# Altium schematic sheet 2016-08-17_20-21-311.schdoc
size 387 x 177 mm; SheetNumber: 1; SheetTotal: 1
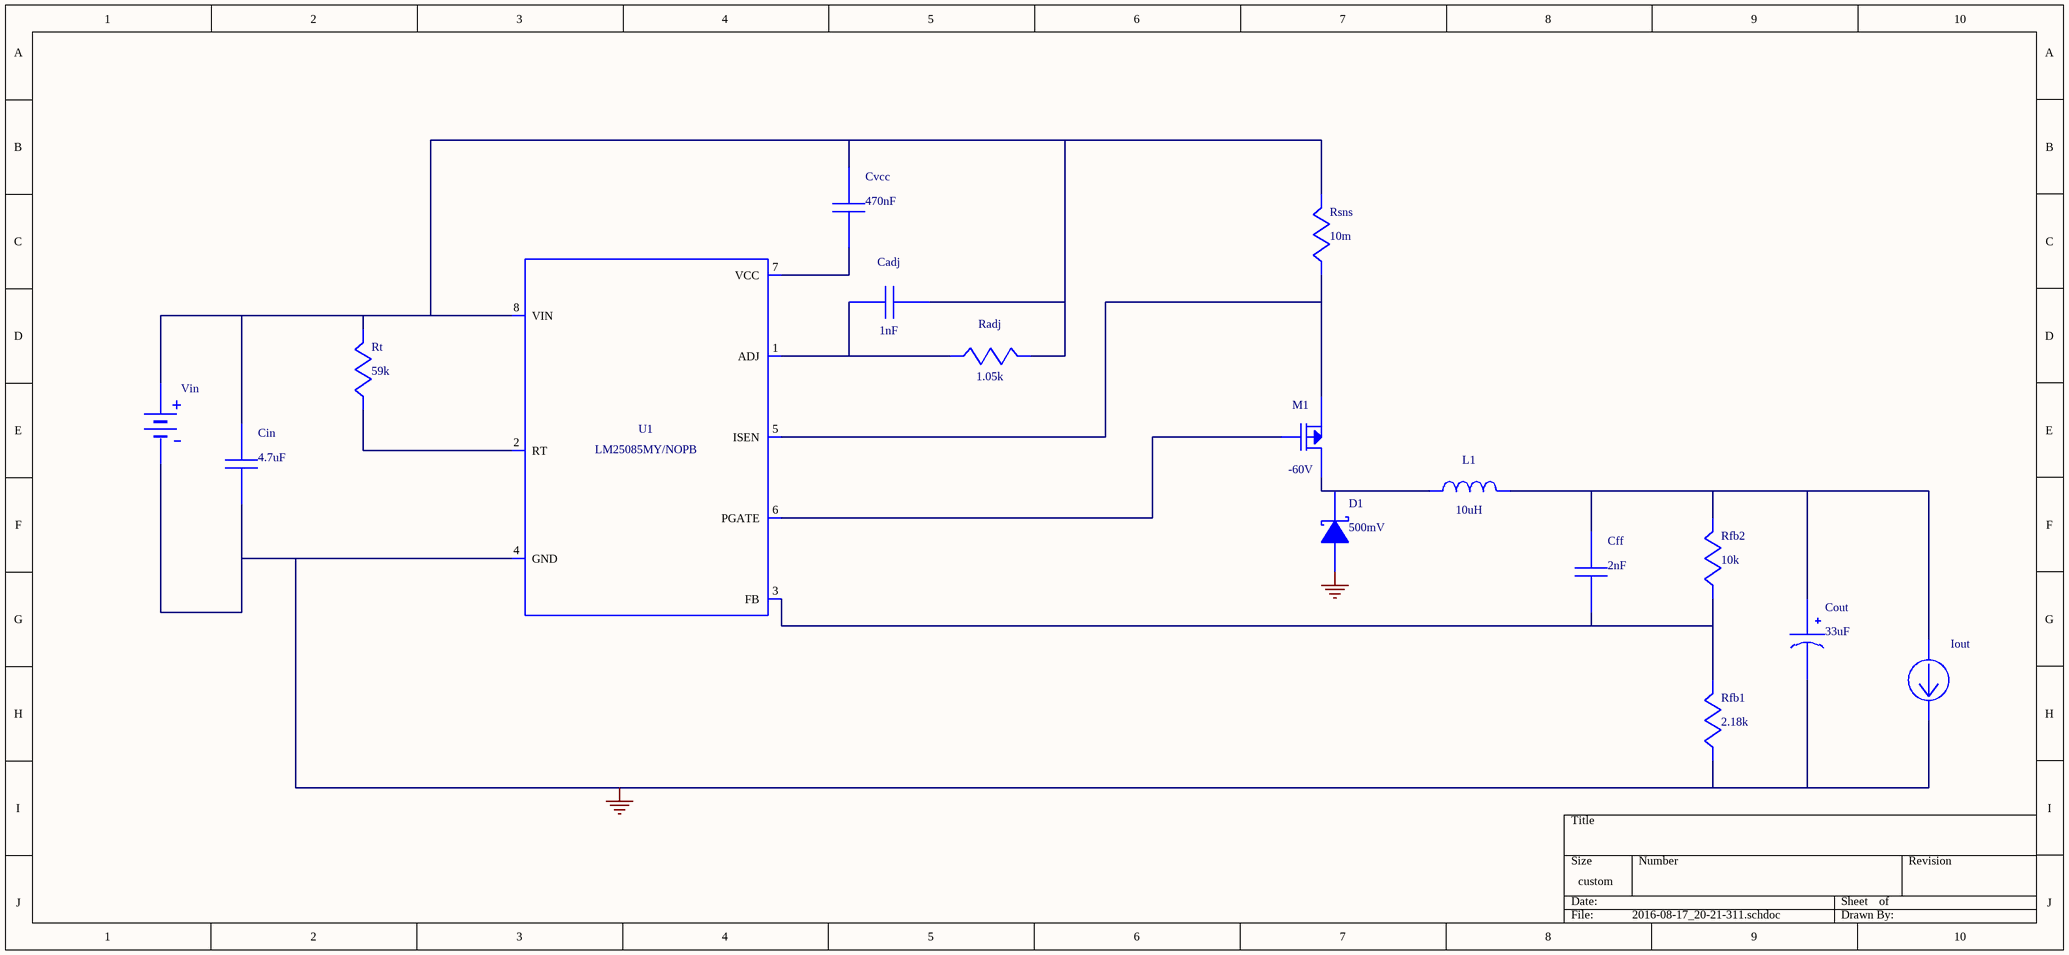
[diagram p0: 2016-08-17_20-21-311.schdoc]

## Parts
Cadj  value 1nF  (hidden comment: CL21C102JBCNFNC)
Cff  value 2nF  (hidden comment: GRM1885C1H202JA01D)
Cin  value 4.7uF  (hidden comment: GRM31CR71H475KA12L)
Cout  value 33uF  (hidden comment: ATPH33MAHA)
Cvcc  value 470nF  (hidden comment: 0805YC474KAT2A)
D1  value 500mV  (hidden comment: B230A-13-F)
Iout  WB_CURRENT_LOAD  (value not drawn)
L1  value 10uH  (hidden comment: VLP8040T-100M)
M1  value -60V  (hidden comment: FDC5614P)
Radj  value 1.05k  (hidden comment: CRCW04021K05FKED)
Rfb1  value 2.18k  (hidden comment: RT0805BRD072K18L)
Rfb2  value 10k  (hidden comment: CRCW040210K0FKED)
Rsns  value 10m  (hidden comment: CSR1206FK10L0)
Rt  value 59k  (hidden comment: CRCW040259K0FKED)
U1  LM5085MY/NOPB  (value not drawn)
Vin  WB_BATTERY  (value not drawn)

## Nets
0: Cin.2 Cout.2(-) D1.2(A) Iout.2(-) Rfb1.2 U1.4(GND) U1.9(EP) Vin.2(-)
NetCadj_1: Cadj.1 Cin.1 Cvcc.1 Radj.1 Rsns.1 Rt.1 U1.8(VIN) Vin.1(+)
NetCadj_2: Cadj.2 Radj.2 U1.1(ADJ)
NetCff_1: Cff.1 Cout.1(+) Iout.1(+) L1.2 Rfb2.1
NetCff_2: Cff.2 Rfb1.1 Rfb2.2 U1.3(FB)
NetCvcc_2: Cvcc.2 U1.7(VCC)
NetD1_1: D1.1(K) L1.1 M1.1(Drain) M1.2(Drain) M1.5(Drain) M1.6(Drain)
NetM1_3: M1.3(Gate) U1.6(PGATE)
NetM1_4: M1.4(Source) Rsns.2 U1.5(ISEN)
NetRt_2: Rt.2 U1.2(RT)

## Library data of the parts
Cadj = CL21C102JBCNFNC: Manufacturer Name: Samsung Electro-Mechanics
Cff = GRM1885C1H202JA01D: GRM1885C1H202JA0; Manufacturer Name: MuRata
Cin = GRM31CR71H475KA12L: GRM31CR71H475KA1; Manufacturer Name: MuRata
Cout = ATPH33MAHA: Manufacturer Name: Panasonic
Cvcc = 0805YC474KAT2A: Manufacturer Name: AVX
D1 = B230A-13-F: Manufacturer Name: Diodes Inc.
L1 = VLP8040T-100M: Unknown; Manufacturer Name: TDK
M1 = FDC5614P: Manufacturer Name: Fairchild Semiconductor
Radj = CRCW04021K05FKED: Manufacturer Name: Vishay-Dale
Rfb1 = RT0805BRD072K18L: Manufacturer Name: Yageo America
Rfb2 = CRCW040210K0FKED: Manufacturer Name: Vishay-Dale
Rsns = CSR1206FK10L0: Manufacturer Name: Stackpole Electronics Inc
Rt = CRCW040259K0FKED: Manufacturer Name: Vishay-Dale
U1 = LM5085MY/NOPB: LM25085MY/NOPB; Manufacturer Name: Texas Instruments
